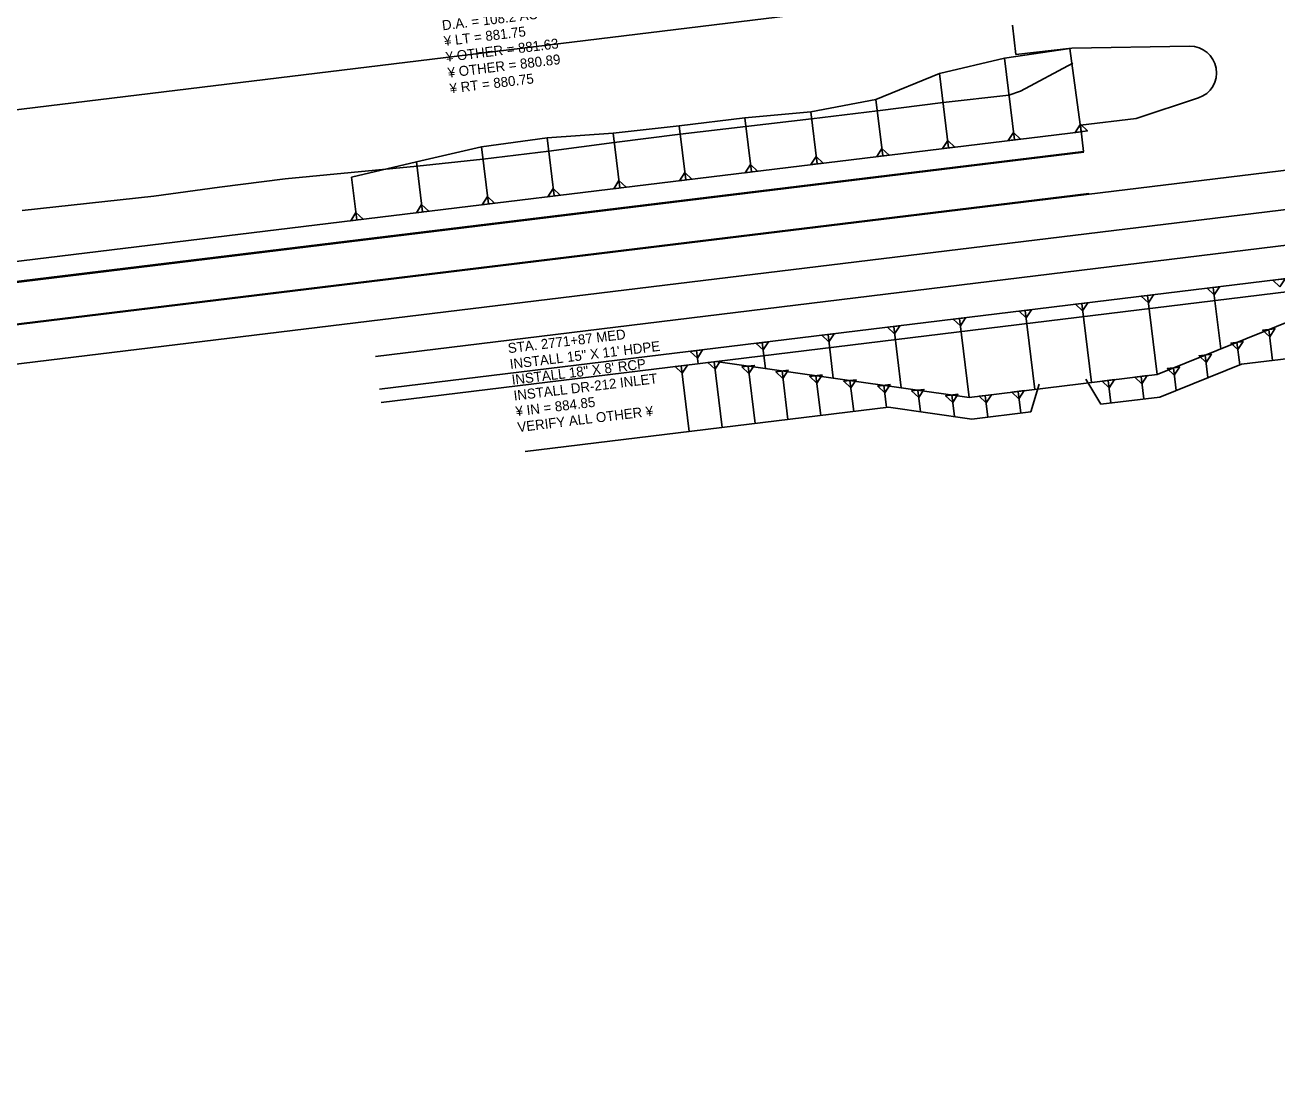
# Model space of a CAD drawing. Extents: x 18436148 to 18440034, y 7649939 to 7652226.
# Drawn here: x 18437956.9 to 18438334.9, y 7649938.6 to 7650259.9 of the extents above; entities that cross this region are included whole.
import ezdxf

# ---------------------------------------------------------------- set-up
doc = ezdxf.new("R2010")
doc.units = 0
for name, color, linetype in [('ATVEHICLE', 7, 'Continuous'), ('Default', 7, 'Continuous'), ('ROWTitleBlock', 7, 'Continuous'), ('TC_Subbase', 7, 'Continuous'), ('TL_ShoulderBtm', 7, 'Continuous'), ('TSOUTLINE', 7, 'Continuous'), ('TSWHEELBASE', 7, 'Continuous')]:
    doc.layers.add(name, color=color, linetype=linetype)

msp = doc.modelspace()

# ---------------------------------------------------------------- linework, layer by layer
at = {"layer": 'ATVEHICLE'}
for p, q in [((18438256.13, 7650250.95), (18438255.05, 7650259.88)), ((18438273.02, 7650252.91), (18438256.13, 7650250.95)), ((18438273.02, 7650252.91), (18438308.57, 7650253.48)), ((18438292.47, 7650231.7), (18438311.2, 7650237.88)), ((18438275.6, 7650229.65), (18438292.47, 7650231.7)), ((18438275.6, 7650229.65), (18438276.57, 7650221.71)), ((18438432.51, 7650227.61), (18437563.42, 7650121.72)), ((18438276.57, 7650221.71), (18437727.63, 7650154.82))]:
    msp.add_line(p, q, dxfattribs=at)
msp.add_arc((18438308.7, 7650245.48), 8, 288.2569, 90.9143, dxfattribs=at)
at = {"layer": 'Default'}
for p, q in [((18438062.74, 7650159.8), (18438398.49, 7650200.8)), ((18438063.95, 7650149.87), (18438399.87, 7650190.89)), ((18438064.43, 7650145.9), (18438401.05, 7650187))]:
    msp.add_line(p, q, dxfattribs=at)
at = {"layer": 'TC_Subbase'}
for p, q in [((18438275.84, 7650227.66), (18438272.43, 7650252.84)), ((18438255.66, 7650225.2), (18438252.66, 7650249.83)), ((18438235.81, 7650222.78), (18438233.06, 7650245.29)), ((18438215.96, 7650220.37), (18438213.87, 7650237.43)), ((18438196.11, 7650217.95), (18438194.18, 7650233.72)), ((18438176.26, 7650215.53), (18438174.25, 7650231.85)), ((18438116.71, 7650208.27), (18438114.54, 7650225.86)), ((18438136.56, 7650210.69), (18438134.52, 7650227.22)), ((18438156.41, 7650213.11), (18438154.4, 7650229.48)), ((18438096.86, 7650205.85), (18438094.73, 7650223.07)), ((18438076.98, 7650203.43), (18438075.14, 7650218.59)), ((18438057.16, 7650201.02), (18438055.55, 7650213.92)), ((18438298.74, 7650154.36), (18438370.48, 7650183.27)), ((18438315.68, 7650180.61), (18438317.94, 7650162.1)), ((18438295.83, 7650178.19), (18438298.74, 7650154.36)), ((18438258.93, 7650173.68), (18438261.84, 7650149.86)), ((18438275.98, 7650175.76), (18438278.89, 7650151.94)), ((18438239.08, 7650171.26), (18438241.99, 7650147.43)), ((18438199.38, 7650166.41), (18438200.98, 7650153.24)), ((18438219.23, 7650168.83), (18438221.49, 7650150.34)), ((18438324.19, 7650157.47), (18438418.38, 7650168.97)), ((18438332.47, 7650167.96), (18438333.61, 7650158.62)), ((18438159.67, 7650161.56), (18438160.16, 7650157.59)), ((18438179.52, 7650163.98), (18438180.48, 7650156.14)), ((18438322.87, 7650164.09), (18438323.7, 7650157.27)), ((18438165, 7650158.18), (18438167.43, 7650138.33)), ((18438241.99, 7650147.43), (18438165.55, 7650158.25)), ((18438313.27, 7650160.22), (18438314.1, 7650153.41)), ((18438155.08, 7650156.97), (18438157.5, 7650137.12)), ((18438175.24, 7650156.88), (18438177.35, 7650139.54)), ((18438185.49, 7650155.43), (18438187.28, 7650140.75)), ((18438195.74, 7650153.98), (18438197.21, 7650141.97)), ((18438241.99, 7650147.43), (18438298.74, 7650154.36)), ((18438299.57, 7650147.55), (18438324.19, 7650157.47)), ((18438303.67, 7650156.35), (18438304.5, 7650149.54)), ((18438205.99, 7650152.53), (18438207.13, 7650143.18)), ((18438216.24, 7650151.08), (18438217.06, 7650144.39)), ((18438263.17, 7650151.44), (18438260.67, 7650143.08)), ((18438281.71, 7650145.37), (18438277.27, 7650152.89)), ((18438283.98, 7650152.56), (18438284.82, 7650145.75)), ((18438293.91, 7650153.77), (18438294.74, 7650146.96)), ((18438226.49, 7650149.63), (18438227.29, 7650143.09)), ((18438236.74, 7650148.18), (18438237.54, 7650141.64)), ((18438246.84, 7650148.03), (18438247.64, 7650141.49)), ((18438256.76, 7650149.24), (18438257.56, 7650142.7)), ((18438281.71, 7650145.37), (18438299.57, 7650147.55)), ((18438217.61, 7650144.46), (18438107.9, 7650131.06)), ((18438242.79, 7650140.89), (18438217.61, 7650144.46)), ((18438242.79, 7650140.89), (18438260.67, 7650143.08))]:
    msp.add_line(p, q, dxfattribs=at)
msp.add_lwpolyline([(18438272.43, 7650252.84), (18438252.66, 7650249.83), (18438233.06, 7650245.29), (18438213.87, 7650237.43), (18438194.18, 7650233.72), (18438174.25, 7650231.85), (18438154.4, 7650229.48), (18438134.52, 7650227.22), (18438114.54, 7650225.86), (18438094.73, 7650223.07), (18438075.14, 7650218.59), (18438055.55, 7650213.92)], dxfattribs=at)
for points in [[(18438275.57, 7650229.9), (18438277.7, 7650227.89), (18438273.98, 7650227.44)], [(18438255.38, 7650227.44), (18438257.52, 7650225.43), (18438253.8, 7650224.98)], [(18438215.68, 7650222.6), (18438217.81, 7650220.59), (18438214.09, 7650220.14)], [(18438235.53, 7650225.02), (18438237.66, 7650223.01), (18438233.94, 7650222.56)], [(18438195.82, 7650220.18), (18438197.96, 7650218.17), (18438194.24, 7650217.72)], [(18438156.12, 7650215.34), (18438158.25, 7650213.33), (18438154.53, 7650212.88)], [(18438175.97, 7650217.76), (18438178.11, 7650215.75), (18438174.38, 7650215.3)], [(18438136.27, 7650212.92), (18438138.4, 7650210.92), (18438134.68, 7650210.46)], [(18438096.56, 7650208.08), (18438098.69, 7650206.08), (18438094.97, 7650205.62)], [(18438116.41, 7650210.5), (18438118.55, 7650208.5), (18438114.82, 7650208.04)], [(18438056.85, 7650203.25), (18438058.99, 7650201.24), (18438055.26, 7650200.79)], [(18438076.67, 7650205.66), (18438078.81, 7650203.65), (18438075.08, 7650203.2)], [(18438315.96, 7650178.38), (18438313.82, 7650180.38), (18438317.55, 7650180.84)], [(18438335.81, 7650180.8), (18438333.68, 7650182.81), (18438337.4, 7650183.26)], [(18438296.1, 7650175.95), (18438293.97, 7650177.96), (18438297.69, 7650178.41)], [(18438259.21, 7650171.45), (18438257.07, 7650173.45), (18438260.79, 7650173.91)], [(18438276.25, 7650173.53), (18438274.12, 7650175.54), (18438277.84, 7650175.99)], [(18438219.5, 7650166.6), (18438217.37, 7650168.61), (18438221.09, 7650169.06)], [(18438239.35, 7650169.02), (18438237.22, 7650171.03), (18438240.94, 7650171.48)], [(18438199.65, 7650164.18), (18438197.51, 7650166.18), (18438201.24, 7650166.64)], [(18438332.75, 7650165.72), (18438330.61, 7650167.73), (18438334.34, 7650168.18)], [(18438159.94, 7650159.33), (18438157.81, 7650161.33), (18438161.53, 7650161.79)], [(18438179.8, 7650161.75), (18438177.66, 7650163.76), (18438181.38, 7650164.21)], [(18438323.15, 7650161.85), (18438321.01, 7650163.86), (18438324.73, 7650164.31)], [(18438165.28, 7650155.95), (18438163.14, 7650157.95), (18438166.86, 7650158.41)], [(18438313.54, 7650157.98), (18438311.41, 7650159.99), (18438315.13, 7650160.45)], [(18438155.35, 7650154.74), (18438153.22, 7650156.74), (18438156.94, 7650157.2)], [(18438175.51, 7650154.65), (18438173.38, 7650156.65), (18438177.1, 7650157.11)], [(18438185.76, 7650153.19), (18438183.63, 7650155.2), (18438187.35, 7650155.66)], [(18438196.01, 7650151.74), (18438193.88, 7650153.75), (18438197.6, 7650154.21)], [(18438294.18, 7650151.54), (18438292.05, 7650153.55), (18438295.77, 7650154)], [(18438303.94, 7650154.12), (18438301.81, 7650156.12), (18438305.53, 7650156.58)], [(18438206.26, 7650150.29), (18438204.13, 7650152.3), (18438207.85, 7650152.75)], [(18438216.51, 7650148.84), (18438214.38, 7650150.85), (18438218.1, 7650151.3)], [(18438284.26, 7650150.33), (18438282.12, 7650152.33), (18438285.84, 7650152.79)], [(18438226.77, 7650147.39), (18438224.63, 7650149.4), (18438228.35, 7650149.85)], [(18438237.02, 7650145.94), (18438234.88, 7650147.95), (18438238.61, 7650148.4)], [(18438247.11, 7650145.79), (18438244.98, 7650147.8), (18438248.7, 7650148.25)], [(18438257.04, 7650147), (18438254.9, 7650149.01), (18438258.63, 7650149.47)]]:
    msp.add_lwpolyline(points, close=True, dxfattribs=at)
at = {"layer": 'TL_ShoulderBtm'}
for p, q in [((18438530.78, 7650304.56), (18436148.4, 7650014.28)), ((18438540.01, 7650228.87), (18436157.63, 7649938.59)), ((18437727.66, 7650154.57), (18438276.6, 7650221.46)), ((18438278.11, 7650209.05), (18437729.19, 7650142.17))]:
    msp.add_line(p, q, dxfattribs=at)
at = {"layer": 'TSOUTLINE'}
msp.add_lwpolyline([(18437956.04, 7650203.83), (18437995.83, 7650208.21), (18438015.62, 7650210.92), (18438035.46, 7650213.46), (18438055.38, 7650215.34), (18438075.29, 7650217.27), (18438095.18, 7650219.39), (18438115.04, 7650221.77), (18438134.86, 7650224.45), (18438154.71, 7650226.93), (18438174.57, 7650229.26), (18438194.43, 7650231.6), (18438214.3, 7650233.93), (18438234.14, 7650236.45), (18438254.01, 7650238.7), (18438257.49, 7650239.94), (18438273.32, 7650248.36)], dxfattribs=at)
at = {"layer": 'TSWHEELBASE'}
msp.add_line((18438275.84, 7650227.66), (18437726.7, 7650160.75), dxfattribs=at)

# ---------------------------------------------------------------- texts
at = {"layer": 'ROWTitleBlock'}
for s, p in [('D.A. = 108.2 AC', (18438083.02, 7650258.27)), ('¥ LT = 881.75', (18438083.6, 7650253.51)), ('¥ OTHER = 881.63', (18438084.18, 7650248.74)), ('¥ OTHER = 880.89', (18438084.76, 7650243.98)), ('¥ RT = 880.75', (18438085.34, 7650239.21)), ('STA. 2771+87 MED', (18438102.91, 7650160.76)), ('INSTALL 15" X 11\' HDPE', (18438103.49, 7650155.99)), ('INSTALL 18" X 8\' RCP', (18438104.07, 7650151.23)), ('INSTALL DR-212 INLET', (18438104.65, 7650146.46)), ('¥ IN = 884.85', (18438105.23, 7650141.7)), ('VERIFY ALL OTHER ¥', (18438105.81, 7650136.93))]:
    msp.add_text(s, height=3, rotation=6.947, dxfattribs=at).set_placement(p)

doc.saveas('drawing.dxf')
